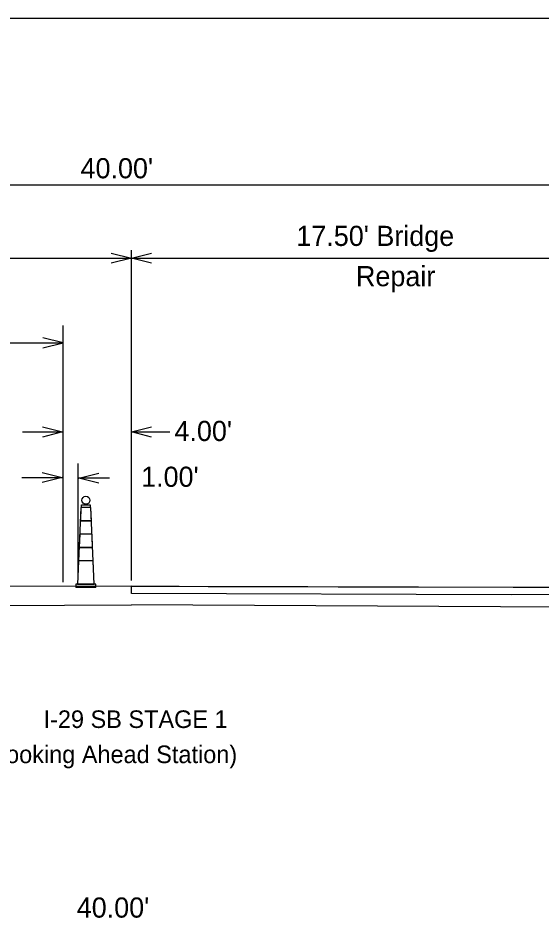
# Model space of a CAD drawing. Extents: x 8771 to 81668, y 6145 to 11018.
# Drawn here: x 15121 to 15711, y 8930 to 9944 of the extents above; entities that cross this region are included whole.
import ezdxf

# ---------------------------------------------------------------- set-up
doc = ezdxf.new("R2010")
doc.units = 0
for name, color, linetype in [('dsnCellElements', 7, 'Continuous'), ('Level 8', 7, 'Continuous'), ('SheetBorder', 7, 'Continuous'), ('ShtPlotIdentification', 7, 'Continuous')]:
    doc.layers.add(name, color=color, linetype=linetype)

msp = doc.modelspace()

# ---------------------------------------------------------------- linework, layer by layer
at = {"layer": 'dsnCellElements'}
for p, q in [((14624.8, 9756.2), (15873.4, 9756.2)), ((15249.1, 9310.1), (15249.1, 9682.4)), ((14624.8, 9673.4), (15249.1, 9673.4)), ((15249.1, 9673.4), (15873.4, 9673.4)), ((15172.1, 9308.4), (15172.1, 9597.6)), ((14898.4, 9578), (15172.1, 9578)), ((15126.2, 9477.6), (15171.6, 9477.6)), ((15249.1, 9477.6), (15292.5, 9477.6)), ((15189.3, 9312.6), (15189.3, 9442)), ((15125.7, 9426.4), (15171.1, 9426.4)), ((15224.4, 9425.6), (15189.7, 9425.6)), ((14683.6, 9279.9), (15249.1, 9282.8)), ((15814.6, 9279.9), (15249.1, 9282.8))]:
    msp.add_line(p, q, dxfattribs=at)
for points in [[(15226.4, 9679.1), (15249.1, 9673.4), (15226.4, 9667.8)], [(15271.8, 9667.8), (15249.1, 9673.4), (15271.8, 9679.1)], [(15149.4, 9572.4), (15172.1, 9578), (15149.4, 9583.7)], [(15148.9, 9483.3), (15171.6, 9477.6), (15148.9, 9471.9)], [(15271.8, 9471.9), (15249.1, 9477.6), (15271.8, 9483.3)], [(15148.4, 9432), (15171.1, 9426.4), (15148.4, 9420.7)], [(15212.4, 9419.9), (15189.7, 9425.6), (15212.4, 9431.3)]]:
    msp.add_lwpolyline(points, dxfattribs=at)
at = {"layer": 'Level 8'}
for p, q in [((15192.2, 9392.5), (15188.5, 9306.2)), ((15192.2, 9392.5), (15191.6, 9377.5)), ((15203.5, 9392.5), (15192.2, 9392.5)), ((15203.5, 9392.5), (15192.2, 9392.5)), ((15207.2, 9306.2), (15203.5, 9392.5)), ((15204.1, 9377.5), (15203.5, 9392.5)), ((15204.1, 9377.5), (15191.6, 9377.5)), ((15191.6, 9377.5), (15204.1, 9377.5)), ((15190.9, 9362.5), (15190.3, 9347.5)), ((15204.8, 9362.5), (15190.9, 9362.5)), ((15204.8, 9362.5), (15190.9, 9362.5)), ((15205.4, 9347.5), (15204.8, 9362.5)), ((15205.4, 9347.5), (15190.3, 9347.5)), ((15190.3, 9347.5), (15205.4, 9347.5)), ((15189.6, 9332.5), (15188.5, 9306.2)), ((15206.1, 9332.5), (15189.6, 9332.5)), ((15206.1, 9332.5), (15189.6, 9332.5)), ((15207.2, 9306.2), (15206.1, 9332.5)), ((15209.1, 9306.2), (15186.6, 9306.2)), ((15186.6, 9306.2), (15186.6, 9302.5)), ((15209.1, 9302.5), (15186.6, 9302.5)), ((15188.5, 9306.2), (15207.2, 9306.2)), ((15209.1, 9302.5), (15209.1, 9306.2))]:
    msp.add_line(p, q, dxfattribs=at)
msp.add_lwpolyline([(15193, 9395.5), (15202.6, 9395.5), (15202.6, 9392.5), (15193, 9392.5)], close=True, dxfattribs=at)
msp.add_circle((15197.8, 9400.6), 4.5, dxfattribs=at)
at = {"layer": 'SheetBorder'}
msp.add_lwpolyline([(13732.5, 9944), (16867.5, 9944), (16867.5, 7924), (13732.5, 7924)], close=True, dxfattribs=at)
at = {"layer": 'ShtPlotIdentification'}
for p, q in [((15249.1, 9303.9), (14624.8, 9302.3)), ((15249.1, 9303.9), (15873.4, 9302.3)), ((15249.1, 9295.5), (15249.1, 9300.1)), ((15677.4, 9294.2), (15249.1, 9295.5))]:
    msp.add_line(p, q, dxfattribs=at)
for points in [[(15249.1, 9300.1), (15249.1, 9303.9), (15258.3, 9303.8), (15276.8, 9303.8), (15302.8, 9303.7), (15335.5, 9303.6), (15382.7, 9303.5), (15447.9, 9303.4), (15482.4, 9303.3), (15679.6, 9302.8)], [(15679.6, 9302.8), (15873.4, 9302.3), (15873.4, 9294.6), (15677.4, 9294.2)]]:
    msp.add_lwpolyline(points, dxfattribs=at)

# ---------------------------------------------------------------- texts
at = {"layer": 'dsnCellElements'}
for s, height, p in [("40.00'", 22.71, (15191.8, 9763.4)), ("17.50' Bridge", 22.709, (15435.1, 9687.2)), ('Repair', 22.71, (15502.3, 9641.8)), ("4.00'", 22.71, (15297.7, 9467.4)), ("1.00'", 22.71, (15260.1, 9415.8)), ('I-29 SB STAGE 1', 19.8, (15150.1, 9144.1)), ('(Looking Ahead Station)', 19.8, (15084.3, 9104.5)), ("40.00'", 22.71, (15187.5, 8930.4))]:
    msp.add_text(s, height=height, dxfattribs=at).set_placement(p)

doc.saveas('drawing.dxf')
